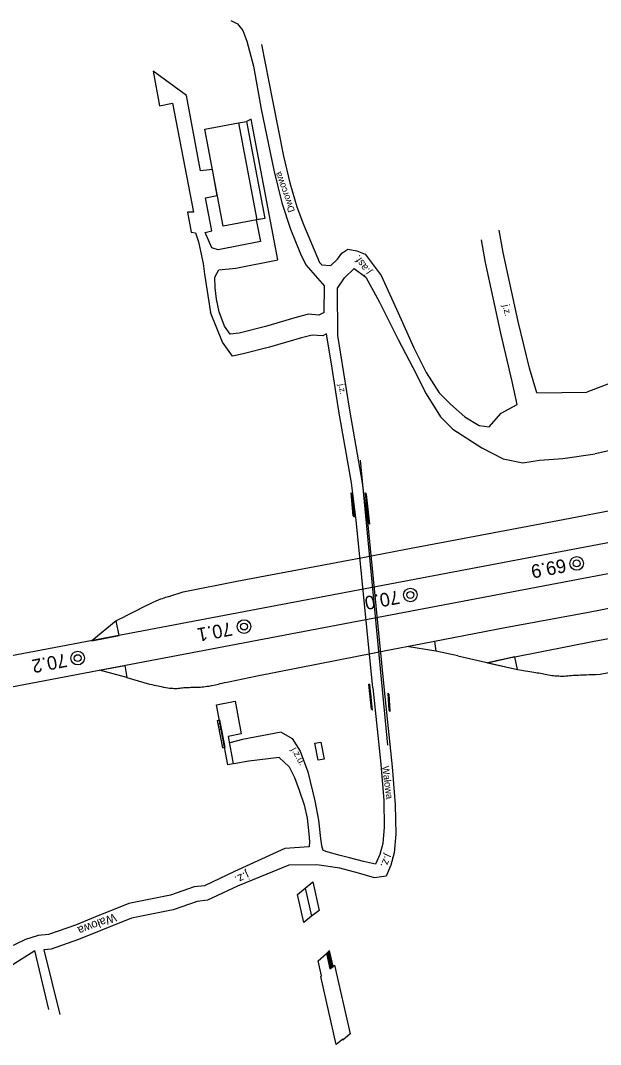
# Model space of a CAD drawing. Extents: x 6541740 to 6566395, y 5525066 to 5530361.
# Drawn here: x 6555056 to 6555141.6, y 5525702 to 5525853.1 of the extents above; entities that cross this region are included whole.
import ezdxf

# ---------------------------------------------------------------- set-up
doc = ezdxf.new("R2010")
doc.units = 0
for name, color, linetype in [('Domyślna', 7, 'Continuous'), ('ps_wymiarowanie', 7, 'Continuous'), ('TOR_PRZEK_P-komponent', 7, 'Continuous'), ('TOR_PS_T-rowy otwarte nieumocnione', 7, 'Continuous'), ('TOR_PS_T-wypelnienia', 7, 'Continuous'), ('TOR_RAMKI-ramka+tabelka 1', 7, 'Continuous'), ('TOR_W-warstwa dodatkowa 2', 7, 'Continuous')]:
    doc.layers.add(name, color=color, linetype=linetype)

# ---------------------------------------------------------------- blocks, each defined once
blk = doc.blocks.new('4010_1')
at = {"layer": 'Domyślna'}
for radius in [0.75, 0.375]:
    blk.add_circle((0, 0), radius, dxfattribs=at)
blk = doc.blocks.new('POINT_DISPLAY')
at = {"layer": 'Domyślna'}
blk.add_line((0, 0), (0, 0), dxfattribs=at)

msp = doc.modelspace()

# ---------------------------------------------------------------- linework, layer by layer
at = {"layer": 'ps_wymiarowanie'}
for p, q in [((6555083.17, 5525837.05), (6555088.16, 5525837.97)), ((6555088.16, 5525837.97), (6555089.32, 5525838.19)), ((6555088.16, 5525837.97), (6555090.87, 5525823.66)), ((6555089.32, 5525838.19), (6555092.03, 5525823.87)), ((6555085.88, 5525822.73), (6555083.17, 5525837.05)), ((6555092.03, 5525823.87), (6555090.87, 5525823.66)), ((6555090.87, 5525823.66), (6555085.88, 5525822.73)), ((6555084.92, 5525752.1), (6555087.65, 5525752.65)), ((6555086.6, 5525743.26), (6555084.92, 5525752.1)), ((6555087.65, 5525752.65), (6555088.57, 5525747.83)), ((6555085.06, 5525749.79), (6555085.42, 5525749.88)), ((6555085.15, 5525749.29), (6555085.52, 5525749.37)), ((6555085.23, 5525748.88), (6555085.6, 5525748.96)), ((6555085.31, 5525748.46), (6555085.68, 5525748.54)), ((6555088.57, 5525747.83), (6555086.61, 5525747.44)), ((6555086.61, 5525747.44), (6555087.37, 5525743.42)), ((6555085.83, 5525745.76), (6555086.19, 5525745.84)), ((6555099.43, 5525746.45), (6555100.33, 5525746.6)), ((6555099.91, 5525743.92), (6555099.43, 5525746.45)), ((6555100.33, 5525746.6), (6555100.8, 5525744.1)), ((6555100.8, 5525744.1), (6555099.91, 5525743.92)), ((6555087.37, 5525743.42), (6555086.6, 5525743.26)), ((6555097.98, 5525725.07), (6555099.11, 5525725.97)), ((6555099.11, 5525725.97), (6555100.06, 5525721.78)), ((6555096.86, 5525724.12), (6555097.98, 5525725.07)), ((6555097.81, 5525720), (6555096.86, 5525724.12)), ((6555097.98, 5525725.07), (6555098.93, 5525720.91)), ((6555100.06, 5525721.78), (6555098.93, 5525720.91)), ((6555098.93, 5525720.91), (6555097.81, 5525720)), ((6555099.91, 5525714.34), (6555101.13, 5525715.42)), ((6555101.59, 5525715.85), (6555101.13, 5525715.42)), ((6555101.13, 5525715.42), (6555101.66, 5525713.13)), ((6555101.13, 5525715.42), (6555101.66, 5525713.13)), ((6555101.24, 5525715.52), (6555101.77, 5525713.22)), ((6555101.34, 5525715.62), (6555101.88, 5525713.31)), ((6555101.45, 5525715.72), (6555101.99, 5525713.4)), ((6555101.56, 5525715.82), (6555102.1, 5525713.48)), ((6555102.13, 5525713.51), (6555101.59, 5525715.85)), ((6555100.42, 5525712.11), (6555099.91, 5525714.34)), ((6555101.66, 5525713.13), (6555102.35, 5525713.69)), ((6555101.66, 5525713.13), (6555102.13, 5525713.51)), ((6555102.35, 5525713.69), (6555104.65, 5525703.58)), ((6555100.32, 5525712.02), (6555100.42, 5525712.11)), ((6555102.59, 5525701.99), (6555100.32, 5525712.02)), ((6555104.65, 5525703.58), (6555103.58, 5525702.65)), ((6555103.55, 5525702.8), (6555102.59, 5525701.99)), ((6555103.58, 5525702.65), (6555103.55, 5525702.8))]:
    msp.add_line(p, q, dxfattribs=at)
for points in [[(6555085.83, 5525745.76), (6555085.15, 5525749.29), (6555085.06, 5525749.79)], [(6555086.19, 5525745.84), (6555085.52, 5525749.37), (6555085.42, 5525749.88)]]:
    msp.add_lwpolyline(points, dxfattribs=at)
at = {"layer": 'TOR_PRZEK_P-komponent'}
for p, q in [((6555221.45, 5525790.95), (6555010.48, 5525750.96)), ((6555222.13, 5525786.49), (6554997.05, 5525743.82))]:
    msp.add_line(p, q, dxfattribs=at)
at = {"layer": 'TOR_PS_T-rowy otwarte nieumocnione'}
for p, q in [((6555106.77, 5525773.91), (6555108.06, 5525774.15)), ((6555128.98, 5525759.21), (6555140.67, 5525761.48)), ((6555108.2, 5525759.77), (6555109.67, 5525760.06)), ((6555120.54, 5525759.31), (6555117.31, 5525760.02)), ((6555120.54, 5525759.31), (6555129.33, 5525757.31))]:
    msp.add_line(p, q, dxfattribs=at)
for points in [[(6555137.14, 5525779.66), (6555149.43, 5525782), (6555161.69, 5525784.33), (6555173.99, 5525786.67), (6555186.25, 5525789)], [(6555108.06, 5525774.15), (6555112.6, 5525775), (6555124.86, 5525777.31), (6555137.14, 5525779.66)], [(6555087.91, 5525770.37), (6555100.2, 5525772.68), (6555106.77, 5525773.91)], [(6555139.85, 5525765.8), (6555152.12, 5525768.17), (6555164.42, 5525770.42), (6555176.66, 5525772.84), (6555188.97, 5525775.16)], [(6555077.88, 5525768.11), (6555080.01, 5525768.78), (6555087.91, 5525770.37)], [(6555140.67, 5525761.48), (6555152.93, 5525763.76), (6555165.23, 5525766.1), (6555177.47, 5525768.45), (6555189.79, 5525770.76)], [(6555117.12, 5525761.49), (6555127.55, 5525763.5), (6555139.85, 5525765.8)], [(6555141.58, 5525756.63), (6555153.84, 5525759.01), (6555166.15, 5525761.33), (6555178.37, 5525763.68), (6555190.7, 5525766.04)], [(6555070.11, 5525764.51), (6555070.11, 5525764.51)], [(6555109.67, 5525760.06), (6555115.3, 5525761.14), (6555117.12, 5525761.49)], [(6555090.67, 5525756.33), (6555102.94, 5525758.73), (6555108.2, 5525759.77)], [(6555124.94, 5525758.31), (6555128.36, 5525759.07), (6555128.98, 5525759.21)], [(6555071.66, 5525756.16), (6555075, 5525755.16)], [(6555086.92, 5525755.56), (6555090.67, 5525756.33)]]:
    msp.add_lwpolyline(points, dxfattribs=at)
for points in [[(6555066.48, 5525761.57), (6555070.54, 5525762.34), (6555070.11, 5525764.51)], [(6555113.02, 5525760.7), (6555115.3, 5525761.14), (6555117.09, 5525761.48), (6555117.31, 5525760.02)], [(6555124.94, 5525758.31), (6555129.33, 5525757.31), (6555128.98, 5525759.21)], [(6555067.62, 5525757.2), (6555071.39, 5525757.91), (6555071.66, 5525756.16)]]:
    msp.add_lwpolyline(points, close=True, dxfattribs=at)
for points in [[(6555070.11, 5525764.51), (6555070.11, 5525764.51), (6555070.11, 5525764.51), (6555070.11, 5525764.51), (6555076.45, 5525767.77), (6555077.18, 5525767.89), (6555077.88, 5525768.11)], [(6555129.33, 5525757.31), (6555130.3, 5525757.15), (6555131.27, 5525757), (6555132.24, 5525756.84), (6555133.21, 5525756.69), (6555134.2, 5525756.44), (6555135.15, 5525756.38), (6555136.24, 5525756.31), (6555137.29, 5525756.46), (6555138.36, 5525756.5), (6555139.43, 5525756.55), (6555140.51, 5525756.59), (6555141.58, 5525756.63)], [(6555075, 5525755.16), (6555076.08, 5525754.96), (6555077.19, 5525754.63), (6555078.25, 5525754.56), (6555079.09, 5525754.5), (6555079.89, 5525754.64), (6555080.71, 5525754.67), (6555081.53, 5525754.71), (6555082.36, 5525754.69), (6555083.17, 5525754.79), (6555084.44, 5525754.95), (6555085.67, 5525755.3), (6555086.92, 5525755.56)]]:
    msp.add_open_spline(points, degree=3, dxfattribs=at)
at = {"layer": 'TOR_PS_T-wypelnienia'}
for p, q in [((6555080.48, 5525842), (6555075.54, 5525845.59)), ((6555075.54, 5525845.59), (6555076.48, 5525840.46)), ((6555082.53, 5525830.87), (6555080.48, 5525842)), ((6555076.48, 5525840.46), (6555078.43, 5525840.85)), ((6555078.43, 5525840.85), (6555081.53, 5525824.8)), ((6555090.05, 5525838.51), (6555089.32, 5525838.19)), ((6555089.32, 5525838.19), (6555092.03, 5525823.87)), ((6555093.97, 5525817.76), (6555090.05, 5525838.51)), ((6555084.3, 5525831.09), (6555082.53, 5525830.87)), ((6555085.03, 5525827.23), (6555084.3, 5525831.09)), ((6555083.28, 5525826.9), (6555085.03, 5525827.23)), ((6555084.24, 5525822.02), (6555083.28, 5525826.9)), ((6555081.53, 5525824.8), (6555080.61, 5525824.81)), ((6555080.61, 5525824.81), (6555081.16, 5525821.86)), ((6555091.34, 5525823.75), (6555090.87, 5525823.66)), ((6555090.87, 5525823.66), (6555090.77, 5525823.64)), ((6555090.77, 5525823.64), (6555091.39, 5525820.45)), ((6555081.16, 5525821.86), (6555081.83, 5525821.73)), ((6555081.83, 5525821.73), (6555082.25, 5525820.39)), ((6555083.22, 5525821.8), (6555084.24, 5525822.02)), ((6555084.22, 5525819.52), (6555083.22, 5525821.8)), ((6555082.25, 5525820.39), (6555082.94, 5525817.22)), ((6555085.16, 5525819.22), (6555084.22, 5525819.52)), ((6555091.39, 5525820.45), (6555085.16, 5525819.22)), ((6555087.77, 5525816.52), (6555093.97, 5525817.76)), ((6555082.94, 5525817.22), (6555083.16, 5525815.66)), ((6555084.67, 5525815.18), (6555085.27, 5525816.3)), ((6555085.27, 5525816.3), (6555087.77, 5525816.52)), ((6555083.16, 5525815.66), (6555084.02, 5525810)), ((6555084.71, 5525813.62), (6555084.67, 5525815.18)), ((6555084.93, 5525811.95), (6555084.71, 5525813.62)), ((6555100.82, 5525810.01), (6555100.86, 5525813.86)), ((6555085.29, 5525810.08), (6555084.93, 5525811.95)), ((6555104.97, 5525783.17), (6555104.79, 5525783.36)), ((6555105.1, 5525780), (6555104.79, 5525783.36)), ((6555105.28, 5525779.81), (6555104.97, 5525783.17)), ((6555107.07, 5525783.2), (6555106.89, 5525783.36)), ((6555107.37, 5525778.89), (6555106.89, 5525783.36)), ((6555107.54, 5525778.74), (6555107.07, 5525783.2)), ((6555105.07, 5525782.13), (6555104.85, 5525782.77)), ((6555105.12, 5525781.5), (6555104.91, 5525782.14)), ((6555107.27, 5525781.31), (6555107.04, 5525781.96)), ((6555105.28, 5525779.81), (6555105.1, 5525780)), ((6555107.34, 5525780.61), (6555107.12, 5525781.26)), ((6555107.98, 5525754.63), (6555105.55, 5525779.33)), ((6555107.2, 5525779.15), (6555109.65, 5525754.29)), ((6555107.54, 5525778.74), (6555107.37, 5525778.89)), ((6555107.54, 5525755.04), (6555107.39, 5525755.17)), ((6555107.79, 5525751.44), (6555107.39, 5525755.17)), ((6555107.94, 5525751.31), (6555107.54, 5525755.04)), ((6555107.72, 5525753.38), (6555107.53, 5525753.9)), ((6555107.78, 5525752.82), (6555107.59, 5525753.34)), ((6555110.19, 5525753.83), (6555110.34, 5525753.64)), ((6555110.19, 5525753.83), (6555110.37, 5525751.31)), ((6555110.34, 5525753.64), (6555110.52, 5525751.12)), ((6555107.94, 5525751.31), (6555107.79, 5525751.44)), ((6555110.28, 5525752.59), (6555110.45, 5525752.08)), ((6555110.31, 5525752.13), (6555110.49, 5525751.62)), ((6555110.37, 5525751.31), (6555110.52, 5525751.12)), ((6555101.06, 5525730.47), (6555100.61, 5525730.67)), ((6555058.6, 5525718.09), (6555056.57, 5525717.41)), ((6555060.15, 5525707.17), (6555058.07, 5525715.88)), ((6555059.4, 5525715.97), (6555061.79, 5525706.4))]:
    msp.add_line(p, q, dxfattribs=at)
for points in [[(6555087, 5525853.07), (6555088.03, 5525852.57), (6555088.78, 5525851.6), (6555089.4, 5525850.03), (6555090.35, 5525846.31), (6555091.51, 5525840), (6555093.37, 5525831), (6555094.57, 5525826.19), (6555095.83, 5525822.3), (6555097.29, 5525818.63), (6555098.1, 5525817.02)], [(6555091.56, 5525849.53), (6555093.16, 5525841.27), (6555094.79, 5525833.07), (6555095.72, 5525829.11), (6555096.76, 5525825.57), (6555097.74, 5525822.99), (6555097.74, 5525822.99), (6555100.12, 5525817.38)], [(6555129.31, 5525796.42), (6555128.54, 5525799.81), (6555126.89, 5525806.92), (6555124.64, 5525817.35), (6555124.03, 5525820.73)], [(6555132.22, 5525798.14), (6555131.13, 5525801.79), (6555129.44, 5525808.65), (6555127.25, 5525818.83), (6555126.64, 5525822.14)], [(6555102.76, 5525817.86), (6555103.41, 5525818.76), (6555104.29, 5525819.32), (6555105.62, 5525819.09), (6555106.87, 5525818.59)], [(6555100.12, 5525817.38), (6555100.46, 5525817.01), (6555101.8, 5525816.9), (6555102.76, 5525817.86)], [(6555106.87, 5525818.59), (6555109.22, 5525815.47), (6555111.71, 5525809.92), (6555114.03, 5525804.77), (6555115.86, 5525801.16), (6555117.76, 5525798.12), (6555119.44, 5525796.45)], [(6555098.1, 5525817.02), (6555100.86, 5525813.86)], [(6555103.82, 5525815.1), (6555105.24, 5525816.49), (6555106.98, 5525815.22), (6555108.97, 5525811.49), (6555111.71, 5525806.01), (6555113.9, 5525801.86), (6555115.87, 5525797.97), (6555117.99, 5525794.58), (6555119.79, 5525792.78)], [(6555102.75, 5525813.58), (6555103.82, 5525815.1)], [(6555107.2, 5525779.15), (6555106.47, 5525784.86), (6555104.58, 5525795.56), (6555102.84, 5525806.59), (6555102.75, 5525813.58)], [(6555100.82, 5525810.01), (6555100.82, 5525810.01), (6555100.03, 5525809.61), (6555098.47, 5525809.72), (6555096.84, 5525809.3), (6555092.14, 5525807.94), (6555088.25, 5525806.92), (6555086.94, 5525806.79), (6555086.09, 5525807.99), (6555085.29, 5525810.08)], [(6555101.17, 5525806.84), (6555101.17, 5525806.84), (6555100.61, 5525806.55), (6555099.03, 5525806.66), (6555097.44, 5525806.25), (6555092.73, 5525804.89), (6555088.83, 5525803.87), (6555087.28, 5525803.53), (6555085.79, 5525805.61), (6555084.02, 5525810)], [(6555105.55, 5525779.33), (6555104.85, 5525784.85), (6555102.97, 5525795.43), (6555101.97, 5525801.78), (6555101.17, 5525806.84), (6555101.17, 5525806.84)], [(6555165.55, 5525805.34), (6555165.55, 5525805.34), (6555158.74, 5525802.27), (6555145.38, 5525800.44), (6555139.57, 5525798.23)], [(6555132.22, 5525798.14), (6555139.57, 5525798.23)], [(6555179.19, 5525798.81), (6555178.27, 5525798.27), (6555177.11, 5525796.01), (6555174.11, 5525795.03), (6555168.85, 5525794.24), (6555160.68, 5525792.4), (6555147.29, 5525790.56), (6555140.81, 5525789.16)], [(6555119.44, 5525796.45), (6555121.59, 5525794.59), (6555123.69, 5525793.33), (6555125.15, 5525793.11), (6555126.95, 5525795.15), (6555129.31, 5525796.42)], [(6555119.79, 5525792.78), (6555124.1, 5525790.01), (6555127.24, 5525788.41), (6555130.13, 5525787.79), (6555132.6, 5525788.19), (6555136.04, 5525788.43), (6555140.81, 5525789.16)], [(6555109.65, 5525754.29), (6555110.83, 5525742.95), (6555111.29, 5525737.35), (6555111.37, 5525733.03), (6555111.16, 5525730.28), (6555110.65, 5525728.44), (6555109.94, 5525726.85), (6555108.24, 5525726.56), (6555105.86, 5525727.26), (6555103.11, 5525728), (6555099.7, 5525728.48)], [(6555107.98, 5525754.63), (6555109.15, 5525743.35), (6555109.6, 5525738.01), (6555109.67, 5525734.05), (6555109.48, 5525731.64), (6555109.03, 5525730), (6555108.4, 5525728.6), (6555106.6, 5525728.97), (6555104.54, 5525729.51), (6555103.16, 5525729.88), (6555101.06, 5525730.47)], [(6555094.45, 5525748.09), (6555088.76, 5525746.97), (6555086.89, 5525746.48)], [(6555094.45, 5525748.09), (6555096.08, 5525747.13), (6555097.27, 5525745.29), (6555098.41, 5525742.2), (6555099.42, 5525737.92), (6555099.95, 5525735.07), (6555100.27, 5525732.38), (6555100.39, 5525731.37), (6555100.61, 5525730.67)], [(6555094.18, 5525744.35), (6555089.69, 5525743.81), (6555087.47, 5525743.4)], [(6555094.17, 5525744.35), (6555095.64, 5525742.97), (6555096.4, 5525741.38), (6555097.12, 5525739.51), (6555097.86, 5525737.35), (6555098.28, 5525735.38), (6555098.54, 5525733.08), (6555098.63, 5525731.95), (6555098.57, 5525731.15)], [(6555098.57, 5525731.15), (6555095, 5525730.9), (6555087.57, 5525727.52), (6555083.16, 5525725.42), (6555081.62, 5525725.24), (6555078.11, 5525724.01), (6555071.95, 5525722.81), (6555068.4, 5525721.36), (6555067.65, 5525721.06), (6555064.08, 5525719.61), (6555060.11, 5525718.2), (6555058.6, 5525718.09)], [(6555099.7, 5525728.48), (6555095.6, 5525728.43), (6555088.01, 5525725.37), (6555083.59, 5525723.27), (6555082.03, 5525723.09), (6555078.53, 5525721.86), (6555072.37, 5525720.65), (6555068.08, 5525718.91), (6555064.51, 5525717.46), (6555060.52, 5525716.05), (6555059.4, 5525715.97), (6555059.4, 5525715.97), (6555059.4, 5525715.97)], [(6555046.51, 5525713.8), (6555047.82, 5525714.2), (6555053.27, 5525715.87), (6555056.57, 5525717.41)], [(6555048.34, 5525711.48), (6555053.81, 5525713.16), (6555058.07, 5525715.88)]]:
    msp.add_lwpolyline(points, dxfattribs=at)
at = {"layer": 'TOR_W-warstwa dodatkowa 2'}
msp.add_line((6555106.1, 5525788.21), (6555110.17, 5525746.15), dxfattribs=at)

# ---------------------------------------------------------------- block references
at = {"layer": 'ps_wymiarowanie', "xscale": 0.30824718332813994, "yscale": 0.8110374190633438, "rotation": -26.43658286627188}
msp.add_blockref('POINT_DISPLAY', (6555101.13, 5525715.42), dxfattribs=at)
at = {"layer": 'TOR_RAMKI-ramka+tabelka 1', "xscale": 1.345963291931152, "yscale": 1.345963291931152}
for p in [(6555138.09, 5525772.97), (6555113.53, 5525768.31), (6555088.97, 5525763.65), (6555064.41, 5525759)]:
    msp.add_blockref('4010_1', p, dxfattribs=at)

# ---------------------------------------------------------------- texts
at = {"layer": 'TOR_PS_T-wypelnienia'}
for s, height, rotation, p in [('Dworcowa', 1, 109.7537, (6555096.5, 5525824.98)), ('j.asf.', 1.111, 125.7268, (6555107.81, 5525816.03)), ('j.z.', 1, 282.1269, (6555127.17, 5525811.05)), ('j.z.', 0.9, 278.9891, (6555102.93, 5525799.39)), ('j.z.u.', 1.007, 298.6638, (6555095.92, 5525745.53)), ('Wałowa', 1.035, 277.3343, (6555109.36, 5525743.03)), ('j.z.', 1.181, 245.917, (6555109.91, 5525730.21)), ('j.z.', 1.248, 205.0108, (6555089.38, 5525727.6)), ('Wałowa', 1.249, 200.5957, (6555069.84, 5525721.37))]:
    msp.add_text(s, height=height, rotation=rotation, dxfattribs=at).set_placement(p)
at = {"layer": 'TOR_RAMKI-ramka+tabelka 1'}
for s, p in [('69.9', (6555136.32, 5525773.67)), ('70.0', (6555111.76, 5525769.02)), ('70.1', (6555087.03, 5525764.33)), ('70.2', (6555062.62, 5525759.7))]:
    msp.add_text(s, height=2, rotation=190.7691, dxfattribs=at).set_placement(p)

doc.saveas('drawing.dxf')
